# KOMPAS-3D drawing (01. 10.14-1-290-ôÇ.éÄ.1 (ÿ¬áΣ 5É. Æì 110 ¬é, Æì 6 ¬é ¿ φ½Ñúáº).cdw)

Views: Вид спереди, Вид сзади. Дверь не показана
Referenced files: Фасад панели А17.cdw
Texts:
  Текст на чертеже
  Размерные надписи
  Шероховатость
  Линия-выноска #1
  Линия-выноска #2
  Линия-выноска #3
  Отклонения формы и база
  Заголовок таблицы
  Ячейка таблицы
  Стрелка вида
  Обозначение изменения
  Фигурная скобка
  Номер узла
  Марка координационной оси
  VRCB
  Выносная надпись
  Обозначение узла
  Марка/позиционное обозначение с линией-выноской
  Марка/позиционное обозначение на линии
  Марка/позиционное обозначение без линии-выноски
  Лит-Масса-Масштаб
  Материал-Предприятие
  Подпись в квадратике
  Normal
  Additional DXF text style 0
  Обычный
  Термин
  Список определений
  Адрес
  Цитаты
  Форматированный
  Courier New
  Z-конец формы
  Z-начало формы
  цепи
  Title Specification
  Body Specification ( left align )
  Body Specificaton ( centered )
  Body Text
  ссылки
  табл
  Без имени
  Тексты. 3,2
  ЗОНА_привяз
  heading 1
  Знак Знак Знак Знак Знак Знак
  Verdana
  Body Text 3
  Title
  txt
  MS Sans Serif
  Simplex
  Txt
  ТекстШаг1
  Денис
  heading 8
  heading 3
  heading 6
  heading 7
  russ
  ООббыыччнныыйй
  ТТееррммиинн
  ССппииссоокк ооппррееддееллеенниийй
  ААддрреесс
  ЦЦииттааттыы
  ФФооррммааттиирроовваанннныыйй
  Z-ккооннеецц ффооррммыы
  Z-ннааччааллоо ффооррммыы
  Абзац Знак
  heading 2
  heading 4
  heading 5
  heading 9
  Клеммник текст
  текст переноса
  Маркировка
  клеммы, контакты
  тексты табл
  AGOpus
  footer
  Аппараты
  подписи
  rustxt
  маркировка
  блок
  скрытый
  желтый
  красный
  Перечень монтажных единиц и чертежей
  Примечания:
  Шкаф выполнить серым цветом габаритными размерами 800х600х2000 мм с цоколем 100 мм;
  Название и надписи шкафа РЗА выполнить черным цветом;
  У всех элементов на внутренней стороне шкафа подписать их позиционные обозначения
  согласно схеме электрической принципиальной 10/14-1-290-УА.Э3.1;
  Промежуточные реле 03-KL1...03-KL6 установить на монтажную плату;
  Предусмотреть ввод кабелей снизу. Монтаж оперативных цепей и цепей сигнализации
  выполнить медным изолированным проводом сечением не менее 1,5 мм 2 , цепи напряжения - 2,5 мм 2 ;
  В нижней части шкафа организовать медную полосу сечением 3х25 мм 2 , прикреплённую к
  основной конструкции на болты. Медная полоса должна обеспечивать возможность присоединения
  кабелей с целью концевой разделки и заземления экранов с помощью металлических зажимов. От шины
  заземления внутри шкафа предусмотреть жгут длинной 700 мм и площадью поперечного сечения
  16 мм 2 , который будет прикручиваться к контуру заземления.
  Монтажная
  единица
  Позиционное
  обозначение
  по схеме
  Место
  надписи
  Текст надписи
  PV1
  SN1
  РA1
  PV2
  SB1
  SN2
  HL1
  HL2
  HL3
  HL4
  HL5
  HL6
  SB2
  PV1. Измерение напряжения 1 с.ш. 110 кВ
  SN1. Измерение напряжения 1 с.ш. 110 кВ
  РА1. Контроль изоляции 1 с.ш. 110 кВ
  PV1. Измерение напряжения 1 с.ш. 6 кВ
  SN1. Измерение напряжения 1 с.ш. 6 кВ
  PV2. Измерение напряжения 2 с.ш. 6 кВ
  SB1. Контроль изоляции 1 с.ш. 110 кВ
  SN2. Измерение напряжения 2 с.ш. 6 кВ
  HL1. Снижение давления элегаза 1ТН-110
  HL2. Аварийное давление 1ТН-110
  HL3. Снижение давления элегаза В-110 1Т
  HL4. Аварийное давление В-110 1Т
  HL5. Снижение давления элегаза В-110 2Т
  HL6. Аварийное давление В-110 2Т
  SB1. Сброс сигнализации
  SB2. Проверка ламп
  В рамке под
  аппаратом
  Наименование монтажной единицы
  TH 110 кВ
  TH 6 кВ
  Элегаз
  Автоматы
  питания
  Общешкафные
  Номер монтажной единицы
  Номер схемы электрической
  принципиальной
  Номер чертежа клеммного ряда
  Перечень надписей (начало)
  5Р. ТН 110 кВ, ТН 6 кВ и элегаз
  А (увеличено)
  Цоколь
  SF4
  SF15
  SF1
  SF7
  SF10
  SF11
  SF14
  SF5
  SF17
  SF20
  Монтажная единица 04
  SF12
  SF13
  SF6
  SF8
  SF9
  SF2
  SF3
  SF16
  SF18
  SF19
  Перечень надписей (окончание)
  SF1. Основная защита 1Т
  SF2. Газовая защита 1Т
  SF3. Резервная защита 1Т
  SF4. Управление В-110 1Т (ЭМВ, ЭМО1)
  SF5. Управление В-110 1Т (ЭМО2)
  SF6. АРКТ 1Т
  SF7. Автоматика охлаждения 1Т
  SF8. Блокирующий комплект ВЛ 110 кВ
  SF9. Питание приемопередатчика Авант Р400
  SF10. Резерв
  SF11. Основная защита 2Т
  SF12. Газовая защита 2Т
  SF13. Резервная защита 2Т
  SF14. Управление В-110 2Т (ЭМВ, ЭМО1)
  SF15. Управление В-110 2Т (ЭМО2)
  SF16. АРКТ 2Т
  SF17. Автоматика охлаждения 2Т
  SF18. Питание измерительных приборов
  SF19. Питание реле-повторителей элегаза
  SF20. Резерв
  Шкаф
  Измерение фазных и
  линейных напряжений
  Ключи
  K5LT_BASIC_RGB_0_0_255_THICK_0.6
  K5LT32769_RGB_0_0_0_THICK_0.6
  K5LT_AXLED_RGB_255_128_0_SC_1_THICK_0.18
  K5LT_THIN_RGB_0_0_0_THICK_0.18
  K5LT32768_RGB_255_0_255_THICK_0.18
  POLYLINE_STYLE_0.60_RGB_0_0_255
  11.09/125.003-290-ЭП.Э3.06-
  Шкаф 5Р. ТН 110 кВ, ТН 6 кВ и элегаз.
  Чертеж общего вида
  Н.контр.
  Разраб.
  Алдошина
  Реконструкция ПС 110 кВ Опорная
  (замена трансформаторов 16МВА на 40МВА)
  Борисов
Dimensions and other numbers on the sheet: 10/14-1-290-УА.ВО.1; 7; 5_заголовок; 2,5_01; 3,2_зона не привяз; 3,2 (надписи); 2.5; 3,2_; 2,5_3; 2,5 (контакты, клеммы); 3,5_01; 2,3_; 3,5_tabl; 3.5; 2,5; 1,8; 3,2; 2.5 курсив; 2,5 грязносинь; 3,5; 5; 3,2 элементы; 3,2 линия; 3,2 таблица; 3.2 маркировка; 2.5_Э5_надписи; 2.5_Э5_ссылки; 2.5_кабель; 3.2; 2.5 надписи; 3,2 (Зоны); 5,0_белый_подчёркнутый; 3.2 фиол; 01; 02; 03; 1 с.ш.; 04; 00; 10/14-1-290-УА.Э3.1; 10/14-1-290-УА.Э4.1; 220; 580; 1400; 400; 530; 270; 00-EL1; 100; 1560; 2100; 1700; 1250; 1390; 800; 250; 550; 350; 450; 01-PV1; 01-SN1; 01-PA1; 01-SB1; 02-PV1; 02-SN1; 02-SN2; 02-PV2; 03-HL1; 03-HL2; 03-HL4; 03-HL3; 03-HL6; 03-HL5; 03-SB2; 03-SB1; 1800; 03-KL1; 03-KL2; 03-KL4; 03-KL3; 03-KL6; 03-KL5; 60; 80; 20; 55; 40; 1520; 1050; 950; 1030; 880; 1180; 1 с.ш. 110 кВ; 0; 1; 11.12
